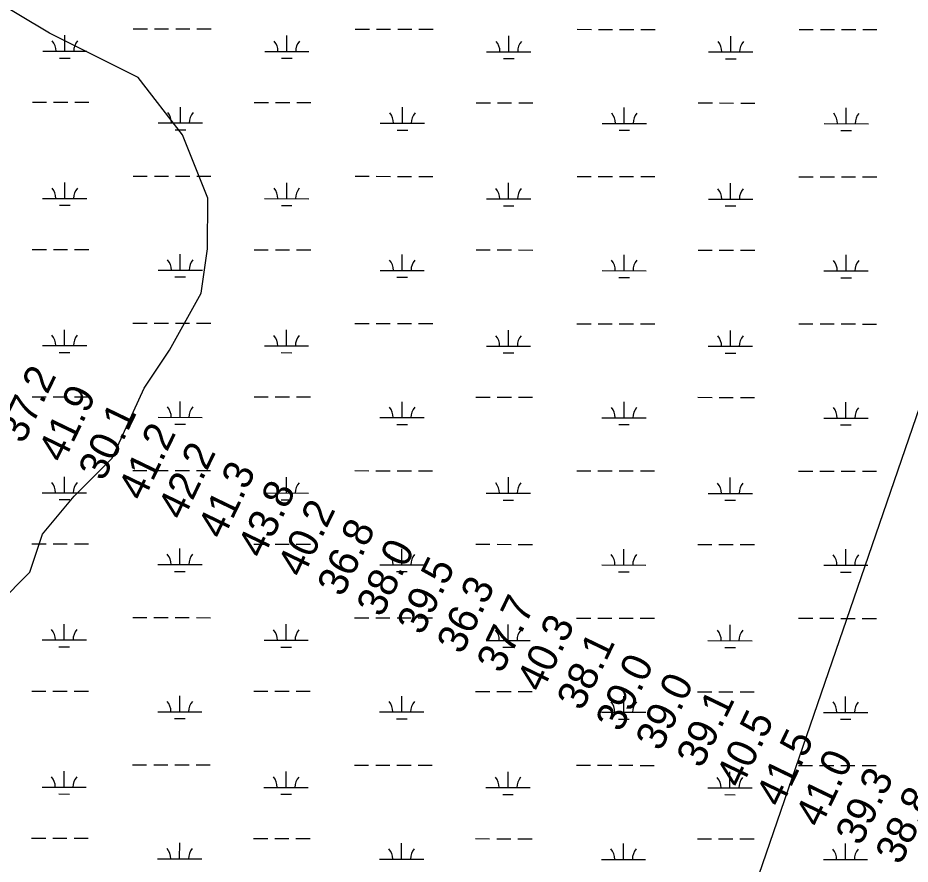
# Model space of a CAD drawing. Extents: x 3148686 to 3186545, y 916144 to 941516.
# Drawn here: x 3155629 to 3157647, y 931075 to 932988 of the extents above; entities that cross this region are included whole.
import ezdxf

# ---------------------------------------------------------------- set-up
doc = ezdxf.new("R2010")
doc.units = 0
for name, color, linetype in [('V-RIVR-RANG', 7, 'Continuous'), ('V-TOPO-BNDY', 7, 'Continuous'), ('V-TOPO-SHOR', 7, 'Continuous'), ('V-WETL-SWMP', 7, 'Continuous')]:
    doc.layers.add(name, color=color, linetype=linetype)

msp = doc.modelspace()

# ---------------------------------------------------------------- linework, layer by layer
at = {"layer": 'V-TOPO-BNDY'}
msp.add_line((3156975.7, 930095.6), (3158547.5, 934665.8), dxfattribs=at)
at = {"layer": 'V-TOPO-SHOR'}
msp.add_lwpolyline([(3155584, 931663.4), (3155655.7, 931735), (3155684.5, 931821), (3155756.2, 931906.9), (3155842.3, 931992.9), (3155914.2, 932150.5), (3155971.6, 932236.4), (3156043.4, 932365.3), (3156057.8, 932465.7), (3156058, 932580.3), (3156000.8, 932723.7), (3155900.6, 932852.8), (3155700, 932953.4), (3155556.8, 933039.5)], dxfattribs=at)
at = {"layer": 'V-WETL-SWMP'}
for p, q in [((3155735.1, 932912.4), (3155735.1, 932948.4)), ((3155889.8, 932962.9), (3155921.8, 932962.9)), ((3155937.8, 932962.9), (3155969.8, 932962.8)), ((3155985.8, 932962.8), (3156017.8, 932962.8)), ((3156033.8, 932962.8), (3156065.8, 932962.7)), ((3156237, 932911.8), (3156237.1, 932947.8)), ((3156391.7, 932962.4), (3156423.7, 932962.4)), ((3156439.7, 932962.4), (3156471.7, 932962.3)), ((3156487.7, 932962.3), (3156519.7, 932962.3)), ((3156535.7, 932962.3), (3156567.7, 932962.2)), ((3156738.9, 932911.3), (3156739, 932947.3)), ((3156893.6, 932961.9), (3156925.6, 932961.8)), ((3156941.6, 932961.8), (3156973.6, 932961.8)), ((3156989.6, 932961.8), (3157021.6, 932961.7)), ((3157037.6, 932961.7), (3157069.6, 932961.7)), ((3157240.8, 932910.8), (3157240.9, 932946.8)), ((3157395.5, 932961.3), (3157427.5, 932961.3)), ((3157443.5, 932961.3), (3157475.5, 932961.3)), ((3157491.5, 932961.2), (3157523.5, 932961.2)), ((3157539.5, 932961.2), (3157571.5, 932961.2)), ((3155685.1, 932912.4), (3155785.1, 932912.3)), ((3156187, 932911.9), (3156287, 932911.8)), ((3156688.9, 932911.3), (3156788.9, 932911.2)), ((3157190.8, 932910.8), (3157290.8, 932910.7)), ((3155723.1, 932896.9), (3155747.1, 932896.9)), ((3156225, 932896.4), (3156249, 932896.4)), ((3156726.9, 932895.9), (3156750.9, 932895.9)), ((3157228.8, 932895.3), (3157252.8, 932895.3)), ((3155661.6, 932797), (3155693.6, 932797)), ((3155709.6, 932796.9), (3155741.6, 932796.9)), ((3155757.6, 932796.9), (3155789.6, 932796.9)), ((3155996.4, 932750.2), (3155996.4, 932786.2)), ((3156163.5, 932796.5), (3156195.5, 932796.4)), ((3156211.5, 932796.4), (3156243.5, 932796.4)), ((3156259.5, 932796.4), (3156291.5, 932796.3)), ((3156498.3, 932749.7), (3156498.3, 932785.7)), ((3156665.4, 932795.9), (3156697.4, 932795.9)), ((3156713.4, 932795.9), (3156745.4, 932795.9)), ((3156761.4, 932795.8), (3156793.4, 932795.8)), ((3157000.2, 932749.2), (3157000.2, 932785.2)), ((3157167.3, 932795.4), (3157199.3, 932795.4)), ((3157215.3, 932795.4), (3157247.3, 932795.3)), ((3157263.3, 932795.3), (3157295.3, 932795.3)), ((3157502.1, 932748.6), (3157502.1, 932784.6)), ((3155946.4, 932750.3), (3156046.4, 932750.2)), ((3156448.3, 932749.7), (3156548.3, 932749.6)), ((3156950.2, 932749.2), (3157050.2, 932749.1)), ((3157452.1, 932748.7), (3157552.1, 932748.6)), ((3155984.4, 932734.8), (3156008.4, 932734.8)), ((3156486.3, 932734.3), (3156510.3, 932734.2)), ((3156988.2, 932733.7), (3157012.2, 932733.7)), ((3157490.1, 932733.2), (3157514.1, 932733.2)), ((3155889.4, 932630.3), (3155921.4, 932630.2)), ((3155937.4, 932630.2), (3155969.4, 932630.2)), ((3155985.4, 932630.2), (3156017.4, 932630.1)), ((3156033.4, 932630.1), (3156065.4, 932630.1)), ((3156391.3, 932629.7), (3156423.3, 932629.7)), ((3156439.3, 932629.7), (3156471.3, 932629.6)), ((3156487.3, 932629.6), (3156519.3, 932629.6)), ((3156535.3, 932629.6), (3156567.3, 932629.5)), ((3156893.2, 932629.2), (3156925.2, 932629.2)), ((3156941.2, 932629.1), (3156973.2, 932629.1)), ((3156989.2, 932629.1), (3157021.2, 932629.1)), ((3157037.2, 932629), (3157069.2, 932629)), ((3157395.1, 932628.7), (3157427.1, 932628.6)), ((3157443.1, 932628.6), (3157475.1, 932628.6)), ((3157491.1, 932628.6), (3157523.1, 932628.5)), ((3157539.1, 932628.5), (3157571.1, 932628.5)), ((3155734.8, 932579.7), (3155734.8, 932615.7)), ((3156236.7, 932579.1), (3156236.7, 932615.1)), ((3156738.6, 932578.6), (3156738.6, 932614.6)), ((3157240.5, 932578.1), (3157240.5, 932614.1)), ((3155684.8, 932579.7), (3155784.8, 932579.6)), ((3155722.7, 932564.3), (3155746.7, 932564.2)), ((3156186.7, 932579.2), (3156286.7, 932579.1)), ((3156224.6, 932563.7), (3156248.6, 932563.7)), ((3156688.6, 932578.7), (3156788.6, 932578.6)), ((3156726.6, 932563.2), (3156750.6, 932563.2)), ((3157190.5, 932578.1), (3157290.5, 932578)), ((3157228.5, 932562.7), (3157252.5, 932562.6)), ((3155661.2, 932464.3), (3155693.2, 932464.3)), ((3155709.2, 932464.3), (3155741.2, 932464.2)), ((3155757.2, 932464.2), (3155789.2, 932464.2)), ((3156163.1, 932463.8), (3156195.1, 932463.8)), ((3156211.1, 932463.7), (3156243.1, 932463.7)), ((3156259.1, 932463.7), (3156291.1, 932463.7)), ((3156665, 932463.3), (3156697, 932463.2)), ((3156713, 932463.2), (3156745, 932463.2)), ((3156761, 932463.2), (3156793, 932463.1)), ((3157167, 932462.7), (3157199, 932462.7)), ((3157215, 932462.7), (3157247, 932462.7)), ((3157263, 932462.6), (3157295, 932462.6)), ((3155996, 932417.5), (3155996.1, 932453.5)), ((3156497.9, 932417), (3156498, 932453)), ((3156999.8, 932416.5), (3156999.9, 932452.5)), ((3157501.7, 932416), (3157501.8, 932452)), ((3155946, 932417.6), (3156046, 932417.5)), ((3155984, 932402.1), (3156008, 932402.1)), ((3156447.9, 932417.1), (3156547.9, 932417)), ((3156485.9, 932401.6), (3156509.9, 932401.6)), ((3156949.8, 932416.5), (3157049.8, 932416.4)), ((3156987.8, 932401.1), (3157011.8, 932401)), ((3157451.7, 932416), (3157551.7, 932415.9)), ((3157489.7, 932400.5), (3157513.7, 932400.5)), ((3155889.1, 932297.6), (3155921.1, 932297.5)), ((3155937.1, 932297.5), (3155969.1, 932297.5)), ((3155985.1, 932297.5), (3156017.1, 932297.4)), ((3156033.1, 932297.4), (3156065.1, 932297.4)), ((3155734.4, 932247), (3155734.4, 932283)), ((3156236.3, 932246.5), (3156236.4, 932282.5)), ((3156391, 932297.1), (3156423, 932297)), ((3156439, 932297), (3156471, 932297)), ((3156487, 932297), (3156519, 932296.9)), ((3156535, 932296.9), (3156567, 932296.9)), ((3156738.2, 932245.9), (3156738.3, 932281.9)), ((3156892.9, 932296.5), (3156924.9, 932296.5)), ((3156940.9, 932296.5), (3156972.9, 932296.4)), ((3156988.9, 932296.4), (3157020.9, 932296.4)), ((3157036.9, 932296.4), (3157068.9, 932296.3)), ((3157240.1, 932245.4), (3157240.2, 932281.4)), ((3157394.8, 932296), (3157426.8, 932296)), ((3157442.8, 932295.9), (3157474.8, 932295.9)), ((3157490.8, 932295.9), (3157522.8, 932295.9)), ((3157538.8, 932295.8), (3157570.8, 932295.8)), ((3155684.4, 932247.1), (3155784.4, 932247)), ((3156186.3, 932246.5), (3156286.3, 932246.4)), ((3156688.2, 932246), (3156788.2, 932245.9)), ((3157190.1, 932245.5), (3157290.1, 932245.4)), ((3155722.4, 932231.6), (3155746.4, 932231.6)), ((3156224.3, 932231.1), (3156248.3, 932231)), ((3156726.2, 932230.5), (3156750.2, 932230.5)), ((3157228.1, 932230), (3157252.1, 932230)), ((3155660.9, 932131.6), (3155692.9, 932131.6)), ((3155708.9, 932131.6), (3155740.9, 932131.6)), ((3155756.9, 932131.5), (3155788.9, 932131.5)), ((3155995.7, 932084.9), (3155995.7, 932120.9)), ((3156162.8, 932131.1), (3156194.8, 932131.1)), ((3156210.8, 932131.1), (3156242.8, 932131)), ((3156258.8, 932131), (3156290.8, 932131)), ((3156497.6, 932084.3), (3156497.6, 932120.3)), ((3156664.7, 932130.6), (3156696.7, 932130.6)), ((3156712.7, 932130.5), (3156744.7, 932130.5)), ((3156760.7, 932130.5), (3156792.7, 932130.5)), ((3156999.5, 932083.8), (3156999.5, 932119.8)), ((3157166.6, 932130.1), (3157198.6, 932130)), ((3157214.6, 932130), (3157246.6, 932130)), ((3157262.6, 932130), (3157294.6, 932129.9)), ((3157501.4, 932083.3), (3157501.4, 932119.3)), ((3155945.7, 932084.9), (3156045.7, 932084.8)), ((3156447.6, 932084.4), (3156547.6, 932084.3)), ((3156949.5, 932083.9), (3157049.5, 932083.8)), ((3157451.4, 932083.3), (3157551.4, 932083.2)), ((3155983.7, 932069.4), (3156007.7, 932069.4)), ((3156485.6, 932068.9), (3156509.6, 932068.9)), ((3156987.5, 932068.4), (3157011.5, 932068.4)), ((3157489.4, 932067.9), (3157513.4, 932067.8)), ((3155888.7, 931964.9), (3155920.7, 931964.9)), ((3155936.7, 931964.9), (3155968.7, 931964.8)), ((3155984.7, 931964.8), (3156016.7, 931964.8)), ((3156032.7, 931964.8), (3156064.7, 931964.7)), ((3156390.6, 931964.4), (3156422.6, 931964.3)), ((3156438.6, 931964.3), (3156470.6, 931964.3)), ((3156486.6, 931964.3), (3156518.6, 931964.2)), ((3156534.6, 931964.2), (3156566.6, 931964.2)), ((3156892.5, 931963.8), (3156924.5, 931963.8)), ((3156940.5, 931963.8), (3156972.5, 931963.8)), ((3156988.5, 931963.7), (3157020.5, 931963.7)), ((3157036.5, 931963.7), (3157068.5, 931963.7)), ((3157394.4, 931963.3), (3157426.4, 931963.3)), ((3157442.4, 931963.3), (3157474.4, 931963.2)), ((3157490.4, 931963.2), (3157522.4, 931963.2)), ((3157538.4, 931963.2), (3157570.4, 931963.1)), ((3155734.1, 931914.3), (3155734.1, 931950.3)), ((3156236, 931913.8), (3156236, 931949.8)), ((3156737.9, 931913.3), (3156737.9, 931949.3)), ((3157239.8, 931912.7), (3157239.8, 931948.7)), ((3155684.1, 931914.4), (3155784.1, 931914.3)), ((3156186, 931913.9), (3156286, 931913.7)), ((3155722, 931898.9), (3155746, 931898.9)), ((3156223.9, 931898.4), (3156247.9, 931898.4)), ((3156687.9, 931913.3), (3156787.9, 931913.2)), ((3156725.9, 931897.9), (3156749.9, 931897.8)), ((3157189.8, 931912.8), (3157289.8, 931912.7)), ((3157227.8, 931897.3), (3157251.8, 931897.3)), ((3155660.5, 931799), (3155692.5, 931798.9)), ((3155708.5, 931798.9), (3155740.5, 931798.9)), ((3155756.5, 931798.9), (3155788.5, 931798.8)), ((3156162.4, 931798.4), (3156194.4, 931798.4)), ((3156210.4, 931798.4), (3156242.4, 931798.4)), ((3156258.4, 931798.3), (3156290.4, 931798.3)), ((3156664.3, 931797.9), (3156696.3, 931797.9)), ((3156712.3, 931797.9), (3156744.3, 931797.8)), ((3156760.3, 931797.8), (3156792.3, 931797.8)), ((3157166.2, 931797.4), (3157198.2, 931797.4)), ((3157214.2, 931797.3), (3157246.2, 931797.3)), ((3157262.2, 931797.3), (3157294.2, 931797.3)), ((3155995.3, 931752.2), (3155995.4, 931788.2)), ((3156497.2, 931751.7), (3156497.3, 931787.7)), ((3156999.1, 931751.1), (3156999.2, 931787.1)), ((3157501, 931750.6), (3157501.1, 931786.6)), ((3155945.3, 931752.2), (3156045.3, 931752.1)), ((3155983.3, 931736.8), (3156007.3, 931736.7)), ((3156447.2, 931751.7), (3156547.2, 931751.6)), ((3156485.2, 931736.2), (3156509.2, 931736.2)), ((3156949.1, 931751.2), (3157049.1, 931751.1)), ((3156987.1, 931735.7), (3157011.1, 931735.7)), ((3157451, 931750.7), (3157551, 931750.6)), ((3157489, 931735.2), (3157513, 931735.2)), ((3155888.4, 931632.2), (3155920.4, 931632.2)), ((3155936.4, 931632.2), (3155968.4, 931632.1)), ((3155984.4, 931632.1), (3156016.4, 931632.1)), ((3156032.4, 931632.1), (3156064.4, 931632)), ((3156390.3, 931631.7), (3156422.3, 931631.7)), ((3156438.3, 931631.7), (3156470.3, 931631.6)), ((3156486.3, 931631.6), (3156518.3, 931631.6)), ((3156534.3, 931631.6), (3156566.3, 931631.5)), ((3155733.7, 931581.7), (3155733.7, 931617.7)), ((3156235.6, 931581.1), (3156235.7, 931617.1)), ((3156737.5, 931580.6), (3156737.6, 931616.6)), ((3156892.2, 931631.2), (3156924.2, 931631.1)), ((3156940.2, 931631.1), (3156972.2, 931631.1)), ((3156988.2, 931631.1), (3157020.2, 931631)), ((3157036.2, 931631), (3157068.2, 931631)), ((3157239.4, 931580.1), (3157239.5, 931616.1)), ((3157394.1, 931630.6), (3157426.1, 931630.6)), ((3157442.1, 931630.6), (3157474.1, 931630.6)), ((3157490.1, 931630.5), (3157522.1, 931630.5)), ((3157538.1, 931630.5), (3157570.1, 931630.5)), ((3155683.7, 931581.7), (3155783.7, 931581.6)), ((3156185.6, 931581.2), (3156285.6, 931581.1)), ((3156687.5, 931580.6), (3156787.5, 931580.5)), ((3157189.4, 931580.1), (3157289.4, 931580)), ((3155721.7, 931566.2), (3155745.7, 931566.2)), ((3156223.6, 931565.7), (3156247.6, 931565.7)), ((3156725.5, 931565.2), (3156749.5, 931565.2)), ((3157227.4, 931564.6), (3157251.4, 931564.6)), ((3155660.2, 931466.3), (3155692.2, 931466.3)), ((3155708.2, 931466.2), (3155740.2, 931466.2)), ((3155756.2, 931466.2), (3155788.2, 931466.2)), ((3155995, 931419.5), (3155995, 931455.5)), ((3156162.1, 931465.8), (3156194.1, 931465.7)), ((3156210.1, 931465.7), (3156242.1, 931465.7)), ((3156258.1, 931465.7), (3156290.1, 931465.6)), ((3156496.9, 931419), (3156496.9, 931455)), ((3156664, 931465.2), (3156696, 931465.2)), ((3156712, 931465.2), (3156744, 931465.2)), ((3156760, 931465.1), (3156792, 931465.1)), ((3156998.8, 931418.5), (3156998.8, 931454.5)), ((3157165.9, 931464.7), (3157197.9, 931464.7)), ((3157213.9, 931464.7), (3157245.9, 931464.6)), ((3157261.9, 931464.6), (3157293.9, 931464.6)), ((3157500.7, 931417.9), (3157500.7, 931453.9)), ((3155945, 931419.6), (3156045, 931419.5)), ((3156446.9, 931419), (3156546.9, 931418.9)), ((3156948.8, 931418.5), (3157048.8, 931418.4)), ((3157450.7, 931418), (3157550.7, 931417.9)), ((3155983, 931404.1), (3156007, 931404.1)), ((3156484.9, 931403.6), (3156508.9, 931403.5)), ((3156986.8, 931403), (3157010.8, 931403)), ((3157488.7, 931402.5), (3157512.7, 931402.5)), ((3155888, 931299.6), (3155920, 931299.5)), ((3155936, 931299.5), (3155968, 931299.5)), ((3155984, 931299.5), (3156016, 931299.4)), ((3156032, 931299.4), (3156064, 931299.4)), ((3156389.9, 931299), (3156421.9, 931299)), ((3156437.9, 931299), (3156469.9, 931298.9)), ((3156485.9, 931298.9), (3156517.9, 931298.9)), ((3156533.9, 931298.9), (3156565.9, 931298.8)), ((3156891.8, 931298.5), (3156923.8, 931298.5)), ((3156939.8, 931298.4), (3156971.8, 931298.4)), ((3156987.8, 931298.4), (3157019.8, 931298.4)), ((3157035.8, 931298.3), (3157067.8, 931298.3)), ((3157393.7, 931298), (3157425.7, 931297.9)), ((3157441.7, 931297.9), (3157473.7, 931297.9)), ((3157489.7, 931297.9), (3157521.7, 931297.8)), ((3157537.7, 931297.8), (3157569.7, 931297.8)), ((3155733.4, 931249), (3155733.4, 931285)), ((3156235.3, 931248.4), (3156235.3, 931284.4)), ((3156737.2, 931247.9), (3156737.2, 931283.9)), ((3157239.1, 931247.4), (3157239.1, 931283.4)), ((3155683.4, 931249), (3155783.4, 931248.9)), ((3156185.3, 931248.5), (3156285.3, 931248.4)), ((3156687.2, 931248), (3156787.2, 931247.9)), ((3155721.3, 931233.6), (3155745.3, 931233.5)), ((3156223.2, 931233), (3156247.2, 931233)), ((3156725.2, 931232.5), (3156749.2, 931232.5)), ((3157189.1, 931247.4), (3157289.1, 931247.3)), ((3157227.1, 931232), (3157251.1, 931231.9)), ((3155659.8, 931133.6), (3155691.8, 931133.6)), ((3155707.8, 931133.6), (3155739.8, 931133.5)), ((3155755.8, 931133.5), (3155787.8, 931133.5)), ((3156161.7, 931133.1), (3156193.7, 931133.1)), ((3156209.7, 931133), (3156241.7, 931133)), ((3156257.7, 931133), (3156289.7, 931133)), ((3156663.6, 931132.6), (3156695.6, 931132.5)), ((3156711.6, 931132.5), (3156743.6, 931132.5)), ((3156759.6, 931132.5), (3156791.6, 931132.4)), ((3157165.5, 931132), (3157197.5, 931132)), ((3157213.5, 931132), (3157245.5, 931132)), ((3157261.5, 931131.9), (3157293.5, 931131.9)), ((3155994.6, 931086.8), (3155994.7, 931122.8)), ((3156496.5, 931086.3), (3156496.6, 931122.3)), ((3156998.4, 931085.8), (3156998.5, 931121.8)), ((3157500.3, 931085.3), (3157500.4, 931121.3)), ((3155944.6, 931086.9), (3156044.6, 931086.8)), ((3156446.5, 931086.4), (3156546.5, 931086.3)), ((3156948.4, 931085.8), (3157048.4, 931085.7)), ((3157450.3, 931085.3), (3157550.3, 931085.2))]:
    msp.add_line(p, q, dxfattribs=at)
for centre, start, end in [((3155679.9, 932912.9), 359.1678, 40.7115), ((3155790.4, 932912.8), 139.1678, 180.7115), ((3156181.8, 932912.4), 359.1678, 40.7115), ((3156292.3, 932912.2), 139.1678, 180.7115), ((3156683.7, 932911.8), 359.1678, 40.7115), ((3156794.2, 932911.7), 139.1678, 180.7115), ((3157185.6, 932911.3), 359.1678, 40.7115), ((3157296.1, 932911.2), 139.1678, 180.7115), ((3155941.1, 932750.7), 359.1678, 40.7115), ((3156051.6, 932750.6), 139.1678, 180.7115), ((3156443, 932750.2), 359.1678, 40.7115), ((3156553.5, 932750.1), 139.1678, 180.7115), ((3156944.9, 932749.7), 359.1678, 40.7115), ((3157055.4, 932749.6), 139.1678, 180.7115), ((3157446.9, 932749.2), 359.1678, 40.7115), ((3157557.3, 932749), 139.1678, 180.7115), ((3155679.5, 932580.2), 359.1678, 40.7115), ((3155790, 932580.1), 139.1678, 180.7115), ((3156181.4, 932579.7), 359.1678, 40.7115), ((3156291.9, 932579.6), 139.1678, 180.7115), ((3156683.3, 932579.2), 359.1678, 40.7115), ((3156793.8, 932579), 139.1678, 180.7115), ((3157185.2, 932578.6), 359.1678, 40.7115), ((3157295.7, 932578.5), 139.1678, 180.7115), ((3155940.8, 932418.1), 359.1678, 40.7115), ((3156051.3, 932418), 139.1678, 180.7115), ((3156442.7, 932417.5), 359.1678, 40.7115), ((3156553.2, 932417.4), 139.1678, 180.7115), ((3156944.6, 932417), 359.1678, 40.7115), ((3157055.1, 932416.9), 139.1678, 180.7115), ((3157446.5, 932416.5), 359.1678, 40.7115), ((3157557, 932416.4), 139.1678, 180.7115), ((3155679.2, 932247.5), 359.1678, 40.7115), ((3155789.7, 932247.4), 139.1678, 180.7115), ((3156181.1, 932247), 359.1678, 40.7115), ((3156291.6, 932246.9), 139.1678, 180.7115), ((3156683, 932246.5), 359.1678, 40.7115), ((3156793.5, 932246.4), 139.1678, 180.7115), ((3157184.9, 932245.9), 359.1678, 40.7115), ((3157295.4, 932245.8), 139.1678, 180.7115), ((3155940.4, 932085.4), 359.1678, 40.7115), ((3156050.9, 932085.3), 139.1678, 180.7115), ((3156442.3, 932084.9), 359.1678, 40.7115), ((3156552.8, 932084.8), 139.1678, 180.7115), ((3156944.2, 932084.3), 359.1678, 40.7115), ((3157054.7, 932084.2), 139.1678, 180.7115), ((3157446.2, 932083.8), 359.1678, 40.7115), ((3157556.6, 932083.7), 139.1678, 180.7115), ((3155678.8, 931914.9), 359.1678, 40.7115), ((3155789.3, 931914.7), 139.1678, 180.7115), ((3156180.7, 931914.3), 359.1678, 40.7115), ((3156291.2, 931914.2), 139.1678, 180.7115), ((3156682.6, 931913.8), 359.1678, 40.7115), ((3156793.1, 931913.7), 139.1678, 180.7115), ((3157184.5, 931913.3), 359.1678, 40.7115), ((3157295, 931913.2), 139.1678, 180.7115), ((3155940.1, 931752.7), 359.1678, 40.7115), ((3156050.6, 931752.6), 139.1678, 180.7115), ((3156442, 931752.2), 359.1678, 40.7115), ((3156552.5, 931752.1), 139.1678, 180.7115), ((3156943.9, 931751.7), 359.1678, 40.7115), ((3157054.4, 931751.5), 139.1678, 180.7115), ((3157445.8, 931751.1), 359.1678, 40.7115), ((3157556.3, 931751), 139.1678, 180.7115), ((3155678.5, 931582.2), 359.1678, 40.7115), ((3155788.9, 931582.1), 139.1678, 180.7115), ((3156180.4, 931581.7), 359.1678, 40.7115), ((3156290.9, 931581.5), 139.1678, 180.7115), ((3156682.3, 931581.1), 359.1678, 40.7115), ((3156792.8, 931581), 139.1678, 180.7115), ((3157184.2, 931580.6), 359.1678, 40.7115), ((3157294.7, 931580.5), 139.1678, 180.7115), ((3155939.7, 931420), 359.1678, 40.7115), ((3156050.2, 931419.9), 139.1678, 180.7115), ((3156441.6, 931419.5), 359.1678, 40.7115), ((3156552.1, 931419.4), 139.1678, 180.7115), ((3156943.5, 931419), 359.1678, 40.7115), ((3157054, 931418.9), 139.1678, 180.7115), ((3157445.5, 931418.5), 359.1678, 40.7115), ((3157555.9, 931418.3), 139.1678, 180.7115), ((3155678.1, 931249.5), 359.1678, 40.7115), ((3155788.6, 931249.4), 139.1678, 180.7115), ((3156180, 931249), 359.1678, 40.7115), ((3156290.5, 931248.9), 139.1678, 180.7115), ((3156681.9, 931248.5), 359.1678, 40.7115), ((3156792.4, 931248.3), 139.1678, 180.7115), ((3157183.8, 931247.9), 359.1678, 40.7115), ((3157294.3, 931247.8), 139.1678, 180.7115), ((3155939.4, 931087.4), 359.1678, 40.7115), ((3156049.9, 931087.3), 139.1678, 180.7115), ((3156441.3, 931086.8), 359.1678, 40.7115), ((3156551.8, 931086.7), 139.1678, 180.7115), ((3156943.2, 931086.3), 359.1678, 40.7115), ((3157053.7, 931086.2), 139.1678, 180.7115), ((3157445.1, 931085.8), 359.1678, 40.7115), ((3157555.6, 931085.7), 139.1678, 180.7115)]:
    msp.add_arc(centre, 35.2, start, end, dxfattribs=at)

# ---------------------------------------------------------------- texts
at = {"layer": 'V-RIVR-RANG'}
for s, p in [('37.2', (3155641.3, 932022.7)), ('41.9', (3155731.4, 931979.2)), ('30.1', (3155822.7, 931938.3)), ('41.2', (3155911.8, 931892.9)), ('42.2', (3156001.9, 931849.6)), ('41.3', (3156092.1, 931806.4)), ('43.8', (3156182.3, 931763.1)), ('40.2', (3156272.4, 931719.9)), ('36.8', (3156362.6, 931676.6)), ('38.0', (3156451.5, 931630.7)), ('39.5', (3156542.9, 931590.1)), ('36.3', (3156633, 931546.8)), ('37.7', (3156723.2, 931503.5)), ('40.3', (3156813.4, 931460.3)), ('38.1', (3156904.5, 931419.1)), ('39.0', (3156992.4, 931371.1)), ('39.0', (3157082.6, 931327.9)), ('39.1', (3157175, 931289.3)), ('40.5', (3157264.1, 931243.9)), ('41.5', (3157354.3, 931200.7)), ('41.0', (3157443.2, 931154.8)), ('39.3', (3157534.6, 931114.2)), ('38.8', (3157624.8, 931070.9))]:
    msp.add_text(s, height=67, rotation=64.2183, dxfattribs=at).set_placement(p)

doc.saveas('drawing.dxf')
